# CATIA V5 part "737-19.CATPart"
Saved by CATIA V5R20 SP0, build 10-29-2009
Part number: 737-19
Definition: NONE
Nomenclature: 737-19
Source: Unknown
Description: 737-19
Bounding box of the stored display mesh (mm): x -25 to 18, y -24.896 to 24.896, z -37 to 15
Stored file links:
  C:\Users\Utente\Desktop\IO LAVORO\3D X SITO CF\X SITO\737\737-19.CATPart
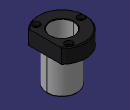
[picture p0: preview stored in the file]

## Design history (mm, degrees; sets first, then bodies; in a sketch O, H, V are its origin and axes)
Body1 "737-19" (main body)
  Solid1: solid without history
